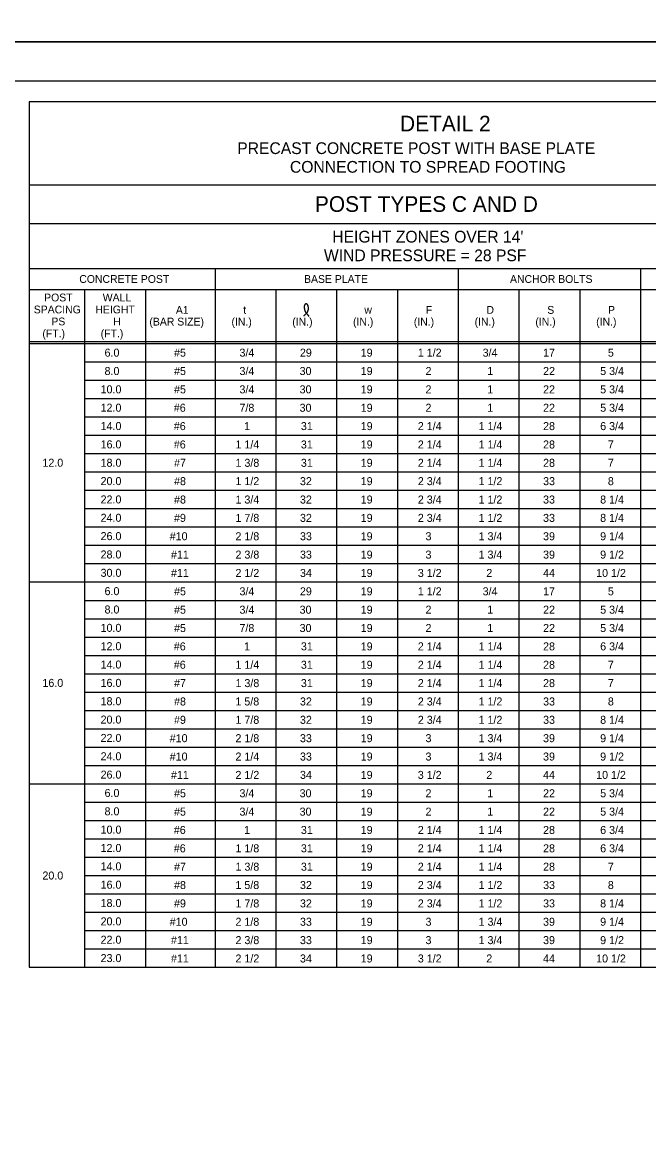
# Model space of a CAD drawing. Extents: x 3351 to 8430, y -3586 to 1457.
# Drawn here: x 6666.3 to 6906.8, y -1036.8 to -608.8 of the extents above; entities that cross this region are included whole.
import ezdxf

# ---------------------------------------------------------------- set-up
doc = ezdxf.new("R2010")
doc.units = 0
for name, color, linetype in [('1', 7, 'Continuous'), ('2', 7, 'Continuous'), ('PLT-BNDY', 7, 'Continuous')]:
    doc.layers.add(name, color=color, linetype=linetype)

msp = doc.modelspace()

# ---------------------------------------------------------------- linework, layer by layer
at = {"layer": '1'}
for p, q in [((6669.01, -639.31), (6669.01, -971.42)), ((7000.34, -639.31), (6669.01, -639.31)), ((7000.34, -671.31), (6669.01, -671.31)), ((6669.01, -686.01), (7000.34, -686.01)), ((6669.01, -703.31), (7000.34, -703.31)), ((6669.01, -703.31), (6737.01, -703.31)), ((6669.01, -703.31), (6737.01, -703.31)), ((6669.01, -703.31), (6737.01, -703.31)), ((6740.34, -703.31), (6740.34, -971.42)), ((6833.68, -703.31), (6833.68, -971.42)), ((6903.68, -703.31), (6903.68, -971.42)), ((6669.01, -711.31), (7000.34, -711.31)), ((6690.34, -971.42), (6690.34, -711.31)), ((6713.68, -711.31), (6713.68, -971.42)), ((6763.68, -711.31), (6763.68, -971.42)), ((6787.01, -711.31), (6787.01, -971.42)), ((6810.34, -711.31), (6810.34, -971.42)), ((6857.01, -711.31), (6857.01, -971.42)), ((6880.34, -711.31), (6880.34, -971.42)), ((6669.01, -731.31), (7000.34, -731.31)), ((6669.01, -732.06), (7000.34, -732.06)), ((6727, -735.58), (6727, -735.58)), ((6752.01, -735.58), (6752.01, -735.58)), ((6775.34, -735.58), (6775.34, -735.58)), ((6798.68, -735.58), (6798.68, -735.58)), ((6822.01, -735.58), (6822.01, -735.58)), ((6845.34, -735.58), (6845.34, -735.58)), ((6868.68, -735.58), (6868.68, -735.58)), ((6892.01, -735.58), (6892.01, -735.58)), ((6690.34, -739.1), (7000.34, -739.1)), ((6690.34, -746.14), (7000.34, -746.14)), ((6690.34, -753.18), (7000.34, -753.18)), ((6690.34, -760.22), (7000.34, -760.22)), ((6690.34, -767.26), (7000.34, -767.26)), ((6690.34, -774.3), (7000.34, -774.3)), ((6690.34, -781.34), (7000.34, -781.34)), ((6690.34, -788.38), (7000.34, -788.38)), ((6690.34, -795.42), (7000.34, -795.42)), ((6690.34, -802.46), (7000.34, -802.46)), ((6690.34, -809.5), (7000.34, -809.5)), ((6690.34, -816.54), (7000.34, -816.54)), ((6669.01, -823.58), (7000.34, -823.58)), ((6690.34, -830.62), (7000.34, -830.62)), ((6690.34, -837.66), (7000.34, -837.66)), ((6690.34, -844.7), (7000.34, -844.7)), ((6690.34, -851.74), (7000.34, -851.74)), ((6690.34, -858.78), (7000.34, -858.78)), ((6690.34, -865.82), (7000.34, -865.82)), ((6690.34, -872.86), (7000.34, -872.86)), ((6690.34, -879.9), (7000.34, -879.9)), ((6690.34, -886.94), (7000.34, -886.94)), ((6690.34, -893.98), (7000.34, -893.98)), ((6669.01, -901.02), (7000.34, -901.02)), ((6690.34, -908.06), (7000.34, -908.06)), ((6690.34, -915.1), (7000.34, -915.1)), ((6690.34, -922.14), (7000.34, -922.14)), ((6690.34, -929.18), (7000.34, -929.18)), ((6690.34, -936.22), (7000.34, -936.22)), ((6690.34, -943.26), (7000.34, -943.26)), ((6690.34, -950.3), (7000.34, -950.3)), ((6690.34, -957.34), (7000.34, -957.34)), ((6690.34, -964.38), (7000.34, -964.38)), ((6669.01, -971.42), (7000.34, -971.42))]:
    msp.add_line(p, q, dxfattribs=at)
msp.add_spline([(6774.4, -721.48), (6774.6, -721.31), (6774.73, -721.18), (6774.93, -720.98), (6775.09, -720.82), (6775.37, -720.61), (6775.56, -720.35), (6775.74, -720.16), (6775.86, -719.93), (6775.97, -719.68), (6776.05, -719.44), (6776.13, -719.21), (6776.16, -719.02), (6776.19, -718.77), (6776.2, -718.55), (6776.19, -718.3), (6776.14, -718.05), (6776.1, -717.81), (6776.04, -717.58), (6775.95, -717.35), (6775.88, -717.22), (6775.78, -717.12), (6775.68, -717.02), (6775.59, -716.94), (6775.48, -716.88), (6775.39, -716.85), (6775.22, -716.85), (6775.13, -716.88), (6774.98, -716.93), (6774.88, -717.01), (6774.82, -717.1), (6774.76, -717.22), (6774.69, -717.33), (6774.65, -717.47), (6774.62, -717.58), (6774.58, -717.82), (6774.56, -717.99), (6774.58, -718.18), (6774.58, -718.38), (6774.62, -718.66), (6774.64, -718.89), (6774.68, -719.06), (6774.75, -719.28), (6774.85, -719.5), (6774.94, -719.7), (6775.04, -719.9), (6775.16, -720.12), (6775.36, -720.3), (6775.48, -720.51), (6775.61, -720.67), (6775.72, -720.85), (6775.86, -721.02), (6776, -721.19), (6776.1, -721.3), (6776.22, -721.43), (6776.32, -721.6)], degree=3, dxfattribs=at)
at = {"layer": '2'}
msp.add_line((6324.34, -631.31), (7110.34, -631.31), dxfattribs=at)
at = {"layer": 'PLT-BNDY'}
for points in [[(6284.34, -22.31), (7125.34, -22.31), (7125.34, -616.31), (6284.34, -616.31)], [(6284.34, -616.31), (7125.34, -616.31), (7125.34, -1210.31), (6284.34, -1210.31)]]:
    msp.add_lwpolyline(points, close=True, dxfattribs=at)

# ---------------------------------------------------------------- texts
at = {"layer": '1'}
for s, height, p in [('DETAIL 2', 6, (6811.36, -650.66)), ('PRECAST CONCRETE POST WITH BASE PLATE', 4.5, (6748.86, -659.36)), ('CONNECTION TO SPREAD FOOTING', 4.5, (6769.09, -666.52)), ('POST TYPES C AND D', 6, (6778.68, -681.54)), ("HEIGHT ZONES OVER 14'", 4.5, (6785.33, -693.32)), ('WIND PRESSURE = 28 PSF', 4.5, (6782.14, -700.48)), ('CONCRETE POST', 3, (6688.22, -708.81)), ('BASE PLATE', 3, (6774.51, -708.81)), ('ANCHOR BOLTS', 3, (6853.58, -708.81)), ('POST', 3, (6674.73, -715.91)), ('WALL', 3, (6697.23, -715.91)), ('SPACING', 3, (6670.74, -720.51)), ('HEIGHT', 3, (6694.4, -720.51)), ('A1', 3, (6725.3, -720.67)), ('t', 3, (6751.17, -720.67)), ('w', 3, (6797.66, -720.67)), ('F', 3, (6821.26, -720.67)), ('D', 3, (6844.54, -720.67)), ('S', 3, (6867.88, -720.67)), ('P', 3, (6891.2, -720.67)), ('PS', 3, (6677.5, -725.11)), ('H', 3, (6701.28, -725.11)), ('(BAR SIZE)', 3, (6715.14, -725.17)), ('(IN.)', 3, (6746.65, -725.17)), ('(IN.)', 3, (6769.98, -725.17)), ('(IN.)', 3, (6793.31, -725.17)), ('(IN.)', 3, (6816.65, -725.17)), ('(IN.)', 3, (6839.98, -725.17)), ('(IN.)', 3, (6863.31, -725.17)), ('(IN.)', 3, (6886.65, -725.17)), ('(FT.)', 3, (6674.06, -729.71)), ('(FT.)', 3, (6696.43, -729.71)), ('6.0', 3.07, (6697.92, -737.11)), ('#5', 3.07, (6724.6, -737.11)), ('3/4', 3.07, (6749.72, -737.11)), ('29', 3.07, (6772.92, -737.11)), ('19', 3.07, (6796.26, -737.11)), ('1 1/2', 3.07, (6818.18, -737.11)), ('3/4', 3.07, (6843.06, -737.11)), ('17', 3.07, (6866.27, -737.11)), ('5', 3.07, (6891.14, -737.11)), ('8.0', 3.07, (6697.92, -744.15)), ('#5', 3.07, (6724.6, -744.16)), ('3/4', 3.07, (6749.72, -744.16)), ('30', 3.07, (6772.8, -744.16)), ('19', 3.07, (6796.26, -744.16)), ('2', 3.07, (6821.14, -744.16)), ('1', 3.07, (6844.82, -744.16)), ('22', 3.07, (6866.27, -744.16)), ('5 3/4', 3.07, (6888.19, -744.16)), ('10.0', 3.07, (6696.4, -751.19)), ('#5', 3.07, (6724.6, -751.2)), ('3/4', 3.07, (6749.72, -751.2)), ('30', 3.07, (6772.8, -751.2)), ('19', 3.07, (6796.26, -751.2)), ('2', 3.07, (6821.14, -751.2)), ('1', 3.07, (6844.82, -751.2)), ('22', 3.07, (6866.27, -751.2)), ('5 3/4', 3.07, (6888.19, -751.2)), ('12.0', 3.07, (6696.4, -758.23)), ('#6', 3.07, (6724.51, -758.25)), ('7/8', 3.07, (6749.71, -758.25)), ('30', 3.07, (6772.8, -758.25)), ('19', 3.07, (6796.26, -758.25)), ('2', 3.07, (6821.14, -758.25)), ('1', 3.07, (6844.82, -758.25)), ('22', 3.07, (6866.27, -758.25)), ('5 3/4', 3.07, (6888.19, -758.25)), ('14.0', 3.07, (6696.4, -765.27)), ('#6', 3.07, (6724.51, -765.29)), ('1', 3.07, (6751.49, -765.29)), ('31', 3.07, (6773.29, -765.29)), ('19', 3.07, (6796.26, -765.29)), ('2 1/4', 3.07, (6818.18, -765.29)), ('1 1/4', 3.07, (6841.51, -765.29)), ('28', 3.07, (6866.27, -765.29)), ('6 3/4', 3.07, (6888.19, -765.29)), ('16.0', 3.07, (6696.4, -772.31)), ('#6', 3.07, (6724.51, -772.34)), ('1 1/4', 3.07, (6748.18, -772.34)), ('31', 3.07, (6773.29, -772.34)), ('19', 3.07, (6796.26, -772.34)), ('2 1/4', 3.07, (6818.18, -772.34)), ('1 1/4', 3.07, (6841.51, -772.34)), ('28', 3.07, (6866.27, -772.34)), ('7', 3.07, (6891.14, -772.34)), ('12.0', 3.07, (6674.07, -779.35)), ('18.0', 3.07, (6696.4, -779.35)), ('#7', 3.07, (6724.6, -779.38)), ('1 3/8', 3.07, (6748.19, -779.38)), ('31', 3.07, (6773.29, -779.38)), ('19', 3.07, (6796.26, -779.38)), ('2 1/4', 3.07, (6818.18, -779.38)), ('1 1/4', 3.07, (6841.51, -779.38)), ('28', 3.07, (6866.27, -779.38)), ('7', 3.07, (6891.14, -779.38)), ('1 1/2', 3.07, (6748.18, -786.42)), ('2 3/4', 3.07, (6818.19, -786.42)), ('1 1/2', 3.07, (6841.51, -786.42)), ('20.0', 3.07, (6696.4, -786.39)), ('#8', 3.07, (6724.6, -786.42)), ('32', 3.07, (6772.94, -786.42)), ('19', 3.07, (6796.26, -786.42)), ('33', 3.07, (6866.27, -786.42)), ('8', 3.07, (6891.14, -786.42)), ('22.0', 3.07, (6696.4, -793.43)), ('#8', 3.07, (6724.6, -793.47)), ('1 3/4', 3.07, (6748.19, -793.47)), ('32', 3.07, (6772.94, -793.47)), ('19', 3.07, (6796.26, -793.47)), ('2 3/4', 3.07, (6818.19, -793.47)), ('1 1/2', 3.07, (6841.51, -793.47)), ('33', 3.07, (6866.27, -793.47)), ('8 1/4', 3.07, (6888.18, -793.47)), ('24.0', 3.07, (6696.4, -800.47)), ('#9', 3.07, (6724.58, -800.51)), ('1 7/8', 3.07, (6748.18, -800.51)), ('32', 3.07, (6772.94, -800.51)), ('19', 3.07, (6796.26, -800.51)), ('2 3/4', 3.07, (6818.19, -800.51)), ('1 1/2', 3.07, (6841.51, -800.51)), ('33', 3.07, (6866.27, -800.51)), ('8 1/4', 3.07, (6888.18, -800.51)), ('26.0', 3.07, (6696.4, -807.51)), ('#10', 3.07, (6722.93, -807.56)), ('2 1/8', 3.07, (6748.18, -807.56)), ('33', 3.07, (6772.94, -807.56)), ('19', 3.07, (6796.26, -807.56)), ('3', 3.07, (6821.14, -807.56)), ('1 3/4', 3.07, (6841.52, -807.56)), ('39', 3.07, (6866.26, -807.56)), ('9 1/4', 3.07, (6888.18, -807.56)), ('28.0', 3.07, (6696.4, -814.55)), ('#11', 3.07, (6723.41, -814.6)), ('2 3/8', 3.07, (6748.19, -814.6)), ('33', 3.07, (6772.94, -814.6)), ('19', 3.07, (6796.26, -814.6)), ('3', 3.07, (6821.14, -814.6)), ('1 3/4', 3.07, (6841.52, -814.6)), ('39', 3.07, (6866.26, -814.6)), ('9 1/2', 3.07, (6888.18, -814.6)), ('30.0', 3.07, (6696.4, -821.59)), ('#11', 3.07, (6723.41, -821.65)), ('2 1/2', 3.07, (6748.18, -821.65)), ('34', 3.07, (6772.94, -821.65)), ('19', 3.07, (6796.26, -821.65)), ('3 1/2', 3.07, (6818.18, -821.65)), ('2', 3.07, (6844.47, -821.65)), ('44', 3.07, (6866.27, -821.65)), ('10 1/2', 3.07, (6886.64, -821.65)), ('6.0', 3.07, (6697.92, -828.63)), ('#5', 3.07, (6724.6, -828.69)), ('3/4', 3.07, (6749.72, -828.69)), ('29', 3.07, (6772.92, -828.69)), ('19', 3.07, (6796.26, -828.69)), ('1 1/2', 3.07, (6818.18, -828.69)), ('3/4', 3.07, (6843.06, -828.69)), ('17', 3.07, (6866.27, -828.69)), ('5', 3.07, (6891.14, -828.69)), ('8.0', 3.07, (6697.92, -835.67)), ('#5', 3.07, (6724.6, -835.74)), ('3/4', 3.07, (6749.72, -835.74)), ('30', 3.07, (6772.8, -835.74)), ('19', 3.07, (6796.26, -835.74)), ('2', 3.07, (6821.14, -835.74)), ('1', 3.07, (6844.82, -835.74)), ('22', 3.07, (6866.27, -835.74)), ('5 3/4', 3.07, (6888.19, -835.74)), ('10.0', 3.07, (6696.4, -842.71)), ('#5', 3.07, (6724.6, -842.78)), ('7/8', 3.07, (6749.71, -842.78)), ('30', 3.07, (6772.8, -842.78)), ('19', 3.07, (6796.26, -842.78)), ('2', 3.07, (6821.14, -842.78)), ('1', 3.07, (6844.82, -842.78)), ('22', 3.07, (6866.27, -842.78)), ('5 3/4', 3.07, (6888.19, -842.78)), ('12.0', 3.07, (6696.4, -849.75)), ('#6', 3.07, (6724.51, -849.82)), ('1', 3.07, (6751.49, -849.82)), ('31', 3.07, (6773.29, -849.82)), ('19', 3.07, (6796.26, -849.82)), ('2 1/4', 3.07, (6818.18, -849.82)), ('1 1/4', 3.07, (6841.51, -849.82)), ('28', 3.07, (6866.27, -849.82)), ('6 3/4', 3.07, (6888.19, -849.82)), ('14.0', 3.07, (6696.4, -856.79)), ('#6', 3.07, (6724.51, -856.87)), ('1 1/4', 3.07, (6748.18, -856.87)), ('31', 3.07, (6773.29, -856.87)), ('19', 3.07, (6796.26, -856.87)), ('2 1/4', 3.07, (6818.18, -856.87)), ('1 1/4', 3.07, (6841.51, -856.87)), ('28', 3.07, (6866.27, -856.87)), ('7', 3.07, (6891.14, -856.87)), ('16.0', 3.07, (6674.07, -863.83)), ('16.0', 3.07, (6696.4, -863.83)), ('#7', 3.07, (6724.6, -863.91)), ('1 3/8', 3.07, (6748.19, -863.91)), ('31', 3.07, (6773.29, -863.91)), ('19', 3.07, (6796.26, -863.91)), ('2 1/4', 3.07, (6818.18, -863.91)), ('1 1/4', 3.07, (6841.51, -863.91)), ('28', 3.07, (6866.27, -863.91)), ('7', 3.07, (6891.14, -863.91)), ('18.0', 3.07, (6696.4, -870.87)), ('#8', 3.07, (6724.6, -870.96)), ('1 5/8', 3.07, (6748.16, -870.96)), ('32', 3.07, (6772.94, -870.96)), ('19', 3.07, (6796.26, -870.96)), ('2 3/4', 3.07, (6818.19, -870.96)), ('1 1/2', 3.07, (6841.51, -870.96)), ('33', 3.07, (6866.27, -870.96)), ('8', 3.07, (6891.14, -870.96)), ('20.0', 3.07, (6696.4, -877.91)), ('#9', 3.07, (6724.58, -878)), ('1 7/8', 3.07, (6748.18, -878)), ('32', 3.07, (6772.94, -878)), ('19', 3.07, (6796.26, -878)), ('2 3/4', 3.07, (6818.19, -878)), ('1 1/2', 3.07, (6841.51, -878)), ('33', 3.07, (6866.27, -878)), ('8 1/4', 3.07, (6888.18, -878)), ('22.0', 3.07, (6696.4, -884.95)), ('#10', 3.07, (6722.93, -885.05)), ('2 1/8', 3.07, (6748.18, -885.05)), ('33', 3.07, (6772.94, -885.05)), ('19', 3.07, (6796.26, -885.05)), ('3', 3.07, (6821.14, -885.05)), ('1 3/4', 3.07, (6841.52, -885.05)), ('39', 3.07, (6866.26, -885.05)), ('9 1/4', 3.07, (6888.18, -885.05)), ('24.0', 3.07, (6696.4, -891.99)), ('#10', 3.07, (6722.93, -892.09)), ('2 1/4', 3.07, (6748.18, -892.09)), ('33', 3.07, (6772.94, -892.09)), ('19', 3.07, (6796.26, -892.09)), ('3', 3.07, (6821.14, -892.09)), ('1 3/4', 3.07, (6841.52, -892.09)), ('39', 3.07, (6866.26, -892.09)), ('9 1/2', 3.07, (6888.18, -892.09)), ('26.0', 3.07, (6696.4, -899.03)), ('#11', 3.07, (6723.41, -899.14)), ('2 1/2', 3.07, (6748.18, -899.14)), ('34', 3.07, (6772.94, -899.14)), ('19', 3.07, (6796.26, -899.14)), ('3 1/2', 3.07, (6818.18, -899.14)), ('2', 3.07, (6844.47, -899.14)), ('44', 3.07, (6866.27, -899.14)), ('10 1/2', 3.07, (6886.64, -899.14)), ('6.0', 3.07, (6697.92, -906.07)), ('3/4', 3.07, (6749.72, -906.18)), ('30', 3.07, (6772.8, -906.18)), ('19', 3.07, (6796.26, -906.18)), ('2', 3.07, (6821.14, -906.18)), ('22', 3.07, (6866.27, -906.18)), ('5 3/4', 3.07, (6888.19, -906.18)), ('#5', 3.07, (6724.6, -906.18)), ('1', 3.07, (6844.82, -906.18)), ('8.0', 3.07, (6697.92, -913.11)), ('#5', 3.07, (6724.6, -913.23)), ('3/4', 3.07, (6749.72, -913.23)), ('30', 3.07, (6772.8, -913.23)), ('19', 3.07, (6796.26, -913.23)), ('2', 3.07, (6821.14, -913.23)), ('1', 3.07, (6844.82, -913.23)), ('22', 3.07, (6866.27, -913.23)), ('5 3/4', 3.07, (6888.19, -913.23)), ('10.0', 3.07, (6696.4, -920.15)), ('#6', 3.07, (6724.51, -920.27)), ('1', 3.07, (6751.49, -920.27)), ('31', 3.07, (6773.29, -920.27)), ('19', 3.07, (6796.26, -920.27)), ('2 1/4', 3.07, (6818.18, -920.27)), ('1 1/4', 3.07, (6841.51, -920.27)), ('28', 3.07, (6866.27, -920.27)), ('6 3/4', 3.07, (6888.19, -920.27)), ('12.0', 3.07, (6696.4, -927.19)), ('#6', 3.07, (6724.51, -927.31)), ('1 1/8', 3.07, (6748.18, -927.31)), ('31', 3.07, (6773.29, -927.31)), ('19', 3.07, (6796.26, -927.31)), ('2 1/4', 3.07, (6818.18, -927.31)), ('1 1/4', 3.07, (6841.51, -927.31)), ('28', 3.07, (6866.27, -927.31)), ('6 3/4', 3.07, (6888.19, -927.31)), ('14.0', 3.07, (6696.4, -934.23)), ('#7', 3.07, (6724.6, -934.36)), ('1 3/8', 3.07, (6748.19, -934.36)), ('31', 3.07, (6773.29, -934.36)), ('19', 3.07, (6796.26, -934.36)), ('2 1/4', 3.07, (6818.18, -934.36)), ('1 1/4', 3.07, (6841.51, -934.36)), ('28', 3.07, (6866.27, -934.36)), ('7', 3.07, (6891.14, -934.36)), ('20.0', 3.07, (6674.07, -937.75)), ('16.0', 3.07, (6696.4, -941.27)), ('#8', 3.07, (6724.6, -941.4)), ('1 5/8', 3.07, (6748.16, -941.4)), ('32', 3.07, (6772.94, -941.4)), ('19', 3.07, (6796.26, -941.4)), ('2 3/4', 3.07, (6818.19, -941.4)), ('1 1/2', 3.07, (6841.51, -941.4)), ('33', 3.07, (6866.27, -941.4)), ('8', 3.07, (6891.14, -941.4)), ('18.0', 3.07, (6696.4, -948.31)), ('#9', 3.07, (6724.58, -948.45)), ('1 7/8', 3.07, (6748.18, -948.45)), ('32', 3.07, (6772.94, -948.45)), ('19', 3.07, (6796.26, -948.45)), ('2 3/4', 3.07, (6818.19, -948.45)), ('1 1/2', 3.07, (6841.51, -948.45)), ('33', 3.07, (6866.27, -948.45)), ('8 1/4', 3.07, (6888.18, -948.45)), ('20.0', 3.07, (6696.4, -955.35)), ('#10', 3.07, (6722.93, -955.49)), ('2 1/8', 3.07, (6748.18, -955.49)), ('33', 3.07, (6772.94, -955.49)), ('19', 3.07, (6796.26, -955.49)), ('3', 3.07, (6821.14, -955.49)), ('1 3/4', 3.07, (6841.52, -955.49)), ('39', 3.07, (6866.26, -955.49)), ('9 1/4', 3.07, (6888.18, -955.49)), ('22.0', 3.07, (6696.4, -962.39)), ('#11', 3.07, (6723.41, -962.54)), ('2 3/8', 3.07, (6748.19, -962.54)), ('33', 3.07, (6772.94, -962.54)), ('19', 3.07, (6796.26, -962.54)), ('3', 3.07, (6821.14, -962.54)), ('1 3/4', 3.07, (6841.52, -962.54)), ('39', 3.07, (6866.26, -962.54)), ('9 1/2', 3.07, (6888.18, -962.54)), ('23.0', 3.07, (6696.4, -969.43)), ('#11', 3.07, (6723.41, -969.58)), ('2 1/2', 3.07, (6748.18, -969.58)), ('34', 3.07, (6772.94, -969.58)), ('19', 3.07, (6796.26, -969.58)), ('3 1/2', 3.07, (6818.18, -969.58)), ('2', 3.07, (6844.47, -969.58)), ('44', 3.07, (6866.27, -969.58)), ('10 1/2', 3.07, (6886.64, -969.58))]:
    msp.add_text(s, height=height, dxfattribs=at).set_placement(p)

doc.saveas('drawing.dxf')
